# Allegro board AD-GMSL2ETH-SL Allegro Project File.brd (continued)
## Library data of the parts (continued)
R206 = RES: User Part Number: UPN; Tolerance: 5; alternate symbols: (R0402L); part number: RES_SM-510,E031796,1/10W,5,R0402; tolerance: 5
R221 R223 R225 = RES: User Part Number: UPN; Tolerance: 1; alternate symbols: (R0402); part number: RES_SM-100K,E003796,1/10W,1,R0402; tolerance: 1
R222 R224 = RES: User Part Number: UPN; Tolerance: 1; alternate symbols: (R0402); part number: RES_SM-15K,E007441,1/10W,1,R0402; tolerance: 1
R227 = RES: User Part Number: UPN; alternate symbols: (R0402L); part number: RES_SM-TBD0402,E004049,TBD0402,TBD0402,R0402
R229 = RES: User Part Number: UPN; Tolerance: 1; alternate symbols: (R0402L); part number: RES_SM-120K,E015615,1/10W,1,R0402; tolerance: 1
R238 = RES: User Part Number: UPN; Tolerance: 1; alternate symbols: (R0402L); part number: RES_SM-8.06K,E021385,1/10W,1,R0402; tolerance: 1
R242 = RES: User Part Number: UPN; Tolerance: 0.1; alternate symbols: (R0603); part number: RES_SM-82K,E040597,1/10W,0.1,R0603; tolerance: 0.1
R243 = RES: User Part Number: UPN; Tolerance: 1; alternate symbols: (R0603); part number: RES_SM-9.1K,E026628,1/10W,1,R0603; tolerance: 1
RT1-RT19 = RESTHERM: Tolerance: 20; User Part Number: UPN; alternate symbols: (R0603H35); part number: RESTHERM_SM-220,E023781,N/A,20,R0603H35; tolerance: 20
S1 S3 S6 = SWSPST4PIN_B: User Part Number: UPN; Tolerance: N/A; alternate symbols: (SWSMSQ236H169); part number: SWSPST4PIN_B_SM-PTS645SK43SMTR92LFS,E019205,SWSMSQ236H169; tolerance: N/A
S2 = SWITCH4: User Part Number: UPN; Tolerance: N/A; alternate symbols: (SWDIP8H335); part number: SWITCH4_TH-CTS206-4,E004560,SWDIP8H335; tolerance: N/A
S12 = SWSPDT: Tolerance: N/A; User Part Number: UPN; alternate symbols: (SWTHL500W260H511); part number: SWSPDT_TH-1101M2S3CQE2,E022397,SWTHL500W260H511; tolerance: N/A
TP1-TP3 TP5 = NCTESTPAD: Tolerance: N/A; User Part Number: UPN; alternate symbols: (TPSMC40); part number: NCTESTPAD_SM-TESTPAD,E019801,TPSMC40; tolerance: N/A
TP6 = CNTP1P: User Part Number: UPN; Tolerance: N/A; alternate symbols: (CNLOOPTP); part number: CNTP1P_TH-RED,E000947,CNLOOPTP; tolerance: N/A
U1 U2 = ADMAX96724: User Part Number: UPN; Tolerance: N/A; alternate symbols: (QFN56_8X8_PAD4_7X4_7H0_8); part number: ADMAX96724_SM-MAX96724GTN/VY+,E061473,QFN56_8X8_PAD4_7X4_7H0_8; tolerance: N/A
U3 = AD9545: User Part Number: UPN; Tolerance: N/A; alternate symbols: (QFN48_7X7_PAD5_6X5_6); part number: AD9545_SM-AD9545BCPZ,E022944,QFN48_7X7_PAD5_6X5_6; tolerance: N/A
U4-U6 U18 = ADLTC330X: User Part Number: UPN; Tolerance: N/A; alternate symbols: (QFN12_2X2_05-08-7072); part number: ADLTC330X_SM-LTC3303ARUCM#TRPBF,E059734,QFN12_2X2_05-08-7072; tolerance: N/A
U7 U8 = ADMAX3182X: Tolerance: N/A; User Part Number: UPN; alternate symbols: (WLCSP6H24); part number: ADMAX3182X_SM-MAX31827ANTABRPF+,E058070,WLCSP6H24; tolerance: N/A
U10 = ADMAX2520X: User Part Number: UPN; Tolerance: N/A; alternate symbols: (QFN20_4X4_PAD2_1X2_1); part number: ADMAX2520X_SM-MAX25206ATPA/VY+,E062128,QFN20_4X4_PAD2_1X2_1; tolerance: N/A
U12 U13 = ADMAX2008X: User Part Number: UPN; Tolerance: N/A; alternate symbols: (QFN20_4X4_PAD2_9X2_9); part number: ADMAX2008X_SM-MAX20087ATPA/VY+,E061551,QFN20_4X4_PAD2_9X2_9; tolerance: N/A
U14 = 741G126: User Part Number: UPN; Tolerance: N/A; alternate symbols: (SOT353); part number: 741G126_SM-74LVC1G126GW,E017822,SOT353; tolerance: N/A
U15 = IC24XX16: Tolerance: N/A; User Part Number: UPN; alternate symbols: (SO8); part number: IC24XX16_SM-24AA16-I/SN,E018010,SO8; tolerance: N/A
U17 = ADM7154: Tolerance: N/A; User Part Number: UPN; alternate symbols: (DFN8_3X3_PAD2_38X1_64); part number: ADM7154_SM-ADM7154ACPZ-3.3,E020267,DFN8_3X3_PAD2_38X1_64; tolerance: N/A
U19 = ICTCA9548A: Tolerance: N/A; User Part Number: UPN; alternate symbols: (QFN24_4X4_PAD2_1X2_1); part number: ICTCA9548A_SM-TCA9548ARGER,E022832,QFN24_4X4_PAD2_1X2_1; tolerance: N/A
U20 U25 = ICPCA9509: User Part Number: UPN; Tolerance: N/A; alternate symbols: (QFN8_1_6X1_6H20); part number: ICPCA9509_SM-PCA9509GM,125,E058249,QFN8_1_6X1_6H20; tolerance: N/A
U21 = ADMAX17573: User Part Number: UPN; Tolerance: N/A; alternate symbols: (QFN24_5X4_PAD3_65X2_65); part number: ADMAX17573_SM-MAX17573ATG+,E060644,QFN24_5X4_PAD3_65X2_65; tolerance: N/A
U22 = ICNVT4857: Tolerance: N/A; User Part Number: UPN; alternate symbols: (WLCSP20-2); part number: ICNVT4857_SM-NVT4857UKAZ,E046591,WLCSP20-2; tolerance: N/A
U23 = ICFT230XQ: Tolerance: N/A; User Part Number: UPN; alternate symbols: (QFN16_4X4_PAD2_1X2_1); part number: ICFT230XQ_SM-FT230XQ-R,E021729,QFN16_4X4_PAD2_1X2_1; tolerance: N/A
U24 = ICFXL2TD245: User Part Number: UPN; Tolerance: N/A; alternate symbols: (QFN10_2_1X1_6); part number: ICFXL2TD245_SM-FXL2TD245L10X,E017923,QFN10_2_1X1_6; tolerance: N/A
U26 = 7407_V4: User Part Number: UPN; Tolerance: N/A; alternate symbols: (SC70-6H43); part number: 7407_V4_SM-SN74LVC2G07DCKR,E055684,SC70-6H43; tolerance: N/A
U27 = ADLTC4355: User Part Number: UPN; Tolerance: N/A; alternate symbols: (DFN14_4X3_PAD3_3X1_7_05-08-1708); part number: ADLTC4355_SM-LTC4355IDE#PBF,E061026,DFN14_4X3_PAD3_3X1_7_05-08-1708; tolerance: N/A
Y1 Y2 = XTAL4PIN_V5: Tolerance: 30PPM; User Part Number: UPN; alternate symbols: (YSML126W98H31); part number: XTAL4PIN_V5_SM-25MEGHZ,E041019,YSML126W98H31; tolerance: 30PPM
Y3 = XTAL4PIN_V9: Tolerance: N/A; User Part Number: UPN; alternate symbols: (YSML79W63H20); part number: XTAL4PIN_V9_SM-52MEGHZ,E062914,YSML79W63H20; tolerance: N/A
Y4 = XTALOCXO4P: Tolerance: N/A; User Part Number: UPN; alternate symbols: (YSML382W295H169); part number: XTALOCXO4P_SM-50MEGHZ,E050311,YSML382W295H169; tolerance: N/A

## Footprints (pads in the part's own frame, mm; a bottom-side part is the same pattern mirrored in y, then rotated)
C0201
  rect 0.305x0.406 smd: 1(-0.318,0) 2(0.318,0)
C0402
  rect 0.483x0.559 smd: 1(-0.45,0) 2(0.45,0)
C0402#2
  rect 0.483x0.559 smd: 1(-0.438,0) 2(0.438,0)
C0402H22
  rect 0.559x0.508 smd: 1(-0.479,0) 2(0.479,0)
C0603
  rect 0.94x0.991 smd: 1(-0.8,0) 2(0.8,0)
C0603#2
  rect 0.762x0.889 smd: 1(-0.7,0) 2(0.7,0)
C0805
  rect 1.143x1.448 smd: 1(-0.9,0) 2(0.9,0)
C0805H53
  rect 1.295x1.6 smd: 1(-0.953,0) 2(0.953,0)
C0805H60
  rect 1.295x1.6 smd: 1(-0.953,0) 2(0.953,0)
C1206H71
  rect 1.6x2.007 smd: 1(-1.397,0) 2(1.397,0)
C1210H110
  rect 1.372x2.794 smd: 1(-1.431,0) 2(1.431,0)
C2220H98
  rect 1.549x5.41 smd: 1(-2.65,0) 2(2.65,0)
CNAMP1888-247
  round 2.794 hole 1.549 unplated: (-4.8,0) (4.8,0)
  rect 0.508x2.007 smd: 1(-3.4,-4.1) 2(-2.6,-4.1) 3(-1.8,-4.1) 4(-1,-4.1) 5(-0.2,-4.1) 6(0.6,-4.1) 7(1.4,-4.1) 8(2.2,-4.1) 9(3,-4.1) 10(3.8,-4.1) 11(3.4,4.1) 12(2.6,4.1) 13(1.8,4.1) 14(1,4.1) 15(0.2,4.1) 16(-0.6,4.1) 17(-1.4,4.1) 18(-2.2,4.1) 19(-3,4.1) 20(-3.8,4.1)
CNHDRRA2X3H451
  round 4.318 hole 2.997 unplated: (-0.013,7.29) (8.395,7.29)
  rect 2.286x2.286 hole 1.778: 1(0,0)
  round 2.286 hole 1.778: 2(4.191,0) 3(8.382,0) 4(0,-5.512) 5(4.191,-5.512) 6(8.382,-5.512)
CNHRSDM3BT-DSF-PEJS
  rect 0.711x1.397 smd: 1(-2.775,7.699) 2(-1.675,7.699) 3(-0.575,7.699) 4(0.525,7.699) 5(1.625,7.699) 6(2.725,7.699) 7(3.825,7.699) 8(4.925,7.699)
  rect 1.194x0.787 smd: A(6.725,-2.7)
  rect 0.711x1.194 smd: B(5.875,7.797)
  rect 0.991x1.397 smd: SH1(-4.675,7.699)
  rect 1.194x1.194 smd: SH2(6.725,3.5)
  rect 1.194x3.2 smd: SH3(6.725,-6.3)
  custom 0.476x0.476 smd: SH4(-6.325,-7.3)
CNJOHNSON142-0701-201
  round 2.032 hole 1.524: 1(0,0) 2(-2.54,2.54) 3(2.54,2.54) 4(2.54,-2.54) 5(-2.54,-2.54)
CNLOOPTP
  round 2.159 hole 1.6: 1(0,0)
CNMOLEX47590-0001
  oval 1.118x0.914 hole 0.864x0.66: (4.45,-2.225) (4.45,2.225)
  rect 1.346x0.406 smd: 1(4.123,-1.3) 2(4.123,-0.65) 3(4.123,0) 4(4.123,0.65) 5(4.123,1.3)
  oval 1.803x1.118 hole 1.295x0.61: SH1(1.45,4.175) SH3(1.45,-4.175)
  rect 1.905x2.896 smd: SH2(1.45,0)
CNMOLEX87832-1420
  round 1.27 hole 1.016 unplated: (-5,0) (5,0)
  rect 0.991x2.743 smd: 1(-6,-2.122) 2(-6,2.122) 3(-4,-2.122) 4(-4,2.122) 5(-2,-2.122) 6(-2,2.122) 7(0,-2.122) 8(0,2.122) 9(2,-2.122) 10(2,2.122) 11(4,-2.122) 12(4,2.122) 13(6,-2.122) 14(6,2.122)
CNPHOENIX1935161
  rect 1.905x1.905 hole 1.397: 1(0,0)
  round 1.905 hole 1.397: 2(5,0)
CNSAMTECTSW-108-08-G-D-ST
  rect 1.651x1.651 hole 1.143: 1(0,0)
  round 1.651 hole 1.143: 2(0,2.54) 3(2.54,0) 4(2.54,2.54) 5(5.08,0) 6(5.08,2.54) 7(7.62,0) 8(7.62,2.54) 9(10.16,0) 10(10.16,2.54) 11(12.7,0) 12(12.7,2.54) 13(15.24,0) 14(15.24,2.54) 15(17.78,0) 16(17.78,2.54)
CNSMMHDR4X60L1686W197H163
  round 1.27 hole 0.94 unplated: (-20.135,1.27) (20.135,0)
  round 0.356 smd: A1(18.73,1.75) A2(18.095,1.75) A3(17.46,1.75) A4(16.825,1.75) A5(16.19,1.75) A6(15.555,1.75) A7(14.92,1.75) A8(14.285,1.75) A9(13.65,1.75) A10(13.015,1.75) A11(12.38,1.75) A12(11.745,1.75) A13(11.11,1.75) A14(10.475,1.75) A15(9.84,1.75) A16(9.205,1.75) A17(8.57,1.75) A18(7.935,1.75) A19(7.3,1.75) A20(6.665,1.75) A21(6.03,1.75) A22(5.395,1.75) A23(4.76,1.75) A24(4.125,1.75) A25(3.49,1.75) A26(2.855,1.75) A27(2.22,1.75) A28(1.585,1.75) A29(0.95,1.75) A30(0.315,1.75) A31(-0.32,1.75) A32(-0.955,1.75) A33(-1.59,1.75) A34(-2.225,1.75) A35(-2.86,1.75) A36(-3.495,1.75) A37(-4.13,1.75) A38(-4.765,1.75) A39(-5.4,1.75) A40(-6.035,1.75) A41(-6.67,1.75) A42(-7.305,1.75) A43(-7.94,1.75) A44(-8.575,1.75) A45(-9.21,1.75) A46(-9.845,1.75) A47(-10.48,1.75) A48(-11.115,1.75) A49(-11.75,1.75) A50(-12.385,1.75) A51(-13.02,1.75) A52(-13.655,1.75) A53(-14.29,1.75) A54(-14.925,1.75) A55(-15.56,1.75) A56(-16.195,1.75) A57(-16.83,1.75) A58(-17.465,1.75) A59(-18.1,1.75) A60(-18.735,1.75) B1(18.73,0.79) B2(18.095,0.79) B3(17.46,0.79) B4(16.825,0.79) B5(16.19,0.79) B6(15.555,0.79) B7(14.92,0.79) B8(14.285,0.79) B9(13.65,0.79) B10(13.015,0.79) B11(12.38,0.79) B12(11.745,0.79) B13(11.11,0.79) B14(10.475,0.79) B15(9.84,0.79) B16(9.205,0.79) B17(8.57,0.79) B18(7.935,0.79) B19(7.3,0.79) B20(6.665,0.79) B21(6.03,0.79) B22(5.395,0.79) B23(4.76,0.79) B24(4.125,0.79) B25(3.49,0.79) B26(2.855,0.79) B27(2.22,0.79) B28(1.585,0.79) B29(0.95,0.79) B30(0.315,0.79) B31(-0.32,0.79) B32(-0.955,0.79) B33(-1.59,0.79) B34(-2.225,0.79) B35(-2.86,0.79) B36(-3.495,0.79) B37(-4.13,0.79) B38(-4.765,0.79) B39(-5.4,0.79) B40(-6.035,0.79) B41(-6.67,0.79) B42(-7.305,0.79) B43(-7.94,0.79) B44(-8.575,0.79) B45(-9.21,0.79) B46(-9.845,0.79) B47(-10.48,0.79) B48(-11.115,0.79) B49(-11.75,0.79) B50(-12.385,0.79) B51(-13.02,0.79) B52(-13.655,0.79) B53(-14.29,0.79) B54(-14.925,0.79) B55(-15.56,0.79) B56(-16.195,0.79) B57(-16.83,0.79) B58(-17.465,0.79) B59(-18.1,0.79) B60(-18.735,0.79) C1(18.73,-0.79) C2(18.095,-0.79) C3(17.46,-0.79) C4(16.825,-0.79) C5(16.19,-0.79) C6(15.555,-0.79) C7(14.92,-0.79) C8(14.285,-0.79) C9(13.65,-0.79) C10(13.015,-0.79) C11(12.38,-0.79) C12(11.745,-0.79) C13(11.11,-0.79) C14(10.475,-0.79) C15(9.84,-0.79) C16(9.205,-0.79) C17(8.57,-0.79) C18(7.935,-0.79) C19(7.3,-0.79) C20(6.665,-0.79) C21(6.03,-0.79) C22(5.395,-0.79) C23(4.76,-0.79) C24(4.125,-0.79) C25(3.49,-0.79) C26(2.855,-0.79) C27(2.22,-0.79) C28(1.585,-0.79) C29(0.95,-0.79) C30(0.315,-0.79) C31(-0.32,-0.79) C32(-0.955,-0.79) C33(-1.59,-0.79) C34(-2.225,-0.79) C35(-2.86,-0.79) C36(-3.495,-0.79) C37(-4.13,-0.79) C38(-4.765,-0.79) C39(-5.4,-0.79) C40(-6.035,-0.79) C41(-6.67,-0.79) C42(-7.305,-0.79) C43(-7.94,-0.79) C44(-8.575,-0.79) C45(-9.21,-0.79) C46(-9.845,-0.79) C47(-10.48,-0.79) C48(-11.115,-0.79) C49(-11.75,-0.79) C50(-12.385,-0.79) C51(-13.02,-0.79) C52(-13.655,-0.79) C53(-14.29,-0.79) C54(-14.925,-0.79) C55(-15.56,-0.79) C56(-16.195,-0.79) C57(-16.83,-0.79) C58(-17.465,-0.79) C59(-18.1,-0.79) C60(-18.735,-0.79) D1(18.73,-1.75) D2(18.095,-1.75) D3(17.46,-1.75) D4(16.825,-1.75) D5(16.19,-1.75) D6(15.555,-1.75) D7(14.92,-1.75) D8(14.285,-1.75) D9(13.65,-1.75) D10(13.015,-1.75) D11(12.38,-1.75) D12(11.745,-1.75) D13(11.11,-1.75) D14(10.475,-1.75) D15(9.84,-1.75) D16(9.205,-1.75) D17(8.57,-1.75) D18(7.935,-1.75) D19(7.3,-1.75) D20(6.665,-1.75) D21(6.03,-1.75) D22(5.395,-1.75) D23(4.76,-1.75) D24(4.125,-1.75) D25(3.49,-1.75) D26(2.855,-1.75) D27(2.22,-1.75) D28(1.585,-1.75) D29(0.95,-1.75) D30(0.315,-1.75) D31(-0.32,-1.75) D32(-0.955,-1.75) D33(-1.59,-1.75) D34(-2.225,-1.75) D35(-2.86,-1.75) D36(-3.495,-1.75) D37(-4.13,-1.75) D38(-4.765,-1.75) D39(-5.4,-1.75) D40(-6.035,-1.75) D41(-6.67,-1.75) D42(-7.305,-1.75) D43(-7.94,-1.75) D44(-8.575,-1.75) D45(-9.21,-1.75) D46(-9.845,-1.75) D47(-10.48,-1.75) D48(-11.115,-1.75) D49(-11.75,-1.75) D50(-12.385,-1.75) D51(-13.02,-1.75) D52(-13.655,-1.75) D53(-14.29,-1.75) D54(-14.925,-1.75) D55(-15.56,-1.75) D56(-16.195,-1.75) D57(-16.83,-1.75) D58(-17.465,-1.75) D59(-18.1,-1.75) D60(-18.735,-1.75)
CNTE2304168-X
  rect 1.168x1.168 hole 0.66: 1(0,0)
  round 1.168 hole 0.66: 2(0,-4) 3(4,-4) 4(4,0)
  round 2.032 hole 1.524: GND1(-2.35,-5.15) GND2(-2.35,1.25) GND3(6.35,-5.15) GND4(6.35,1.25)
  rect 0.991x3.302 smd: GND5(2,-4.501)
  rect 0.991x2.997 smd: GND6(2,0.249)
  rect 2.692x0.991 smd: GND7(-0.146,-2.05) GND8(4.146,-2.05)
  rect 1.041x3.607 smd: GND9(-2.641,-2.05) GND10(6.641,-2.05)
CNTHMHDR1X4L402W230H402
  round 1.778 hole 1.245 unplated: (5.08,2.16)
  rect 1.651x1.651 hole 1.143: 1(0,0)
  round 1.651 hole 1.143: 2(2.54,0) 3(5.08,0) 4(7.62,0)
CNTHMHDR2X4L400W200H330
  rect 1.651x1.651 hole 1.143: 1(0,0)
  round 1.651 hole 1.143: 2(0,2.54) 3(2.54,0) 4(2.54,2.54) 5(5.08,0) 6(5.08,2.54) 7(7.62,0) 8(7.62,2.54)
CPLSMSQ406H488
  rect 4.394x1.905 smd: N(4.347,0) P(-4.347,0)
D0201
  rect 0.229x0.381 smd: A(0.22,0) C(-0.22,0)
DFN8_3X3_PAD2_38X1_64
  oval 0.305x0.838 smd: 1(-0.75,-1.45) 2(-0.25,-1.45) 3(0.25,-1.45) 4(0.75,-1.45) 5(0.75,1.45) 6(0.25,1.45) 7(-0.25,1.45) 8(-0.75,1.45)
  rect 2.388x1.651 smd: PAD(0,0)
DFN14_4X3_PAD3_3X1_7_05-08-1708
  oval 0.254x0.914 smd: 1(-1.5,-1.557) 2(-1,-1.557) 3(-0.5,-1.557) 4(0,-1.557) 5(0.5,-1.557) 6(1,-1.557) 7(1.5,-1.557) 8(1.5,1.557) 9(1,1.557) 10(0.5,1.557) 11(0,1.557) 12(-0.5,1.557) 13(-1,1.557) 14(-1.5,1.557)
  rect 3.302x1.702 smd: 15(0,0)
DO214AB-4
  rect 2.388x3.277 smd: A(3.289,0) C(-3.289,0)
F1206H60
  rect 1.016x1.803 smd: 1(-1.41,0) 2(1.41,0)
FLSML476W358H146
  rect 3.81x2.489 smd: 1(-6.845,2.1) 2(6.845,2.1) 3(-6.845,-2.1) 4(6.845,-2.1)
  rect 7.899x2.311 smd: 5(1,-5.094)
  rect 3.404x2.311 smd: 6(3.25,5.094)
L0402
  rect 0.584x0.711 smd: 1(-0.475,0) 2(0.475,0)
L0806H39
  rect 0.787x1.6 smd: 1(-0.894,0) 2(0.894,0)
L1210H118
  rect 0.66x2.642 smd: 1(-1.27,0) 2(1.27,0)
L7144
  rect 0.635x1.016 smd: 1(-0.635,0) 2(0.635,0)
LED0603
  rect 0.965x0.762 smd: A(0.8,0) C(-0.8,0)
LSMSQ157H122
  rect 0.965x3.708 smd: 1(-1.181,0) 2(1.181,0)
LSMSQ236H98
  custom 0.575x0.575 smd: 1(-2.153,0) 2(2.153,0)
LSMSQ240H126
  custom 0.502x0.502 smd: 1(-2.756,0) 2(2.756,0)
MTE2007194-1
  round 1.524 hole 1.016: GND1(-4.795,6.2) GND2(0.005,6.2) GND3(4.805,6.2) GND5(7.125,1.6) GND6(7.125,-3.4) GND8(7.125,-8.1) GND15(-7.125,-8.1) GND16(-7.125,-3.4) GND18(-7.125,1.6)
  round 1.651 hole 1.143: GND4(7.125,4.1) GND7(7.125,-5.9) GND9(7.125,-15.9) GND10(7.125,-25.9) GND11(1.455,-30.9) GND12(-7.125,-30.9) GND13(-7.125,-20.9) GND14(-7.125,-10.9) GND19(-1.445,-10.9) GND20(3.955,-10.9)
  round 1.397 hole 0.889: GND17(-7.125,-0.9)
POWER33H31
  rect 0.432x0.711 smd: 1(-0.975,-1.404) 2(-0.325,-1.404) 3(0.325,-1.404) 4(0.975,-1.404)
  custom 0.54x0.54 smd: 5(0.97,1.531)
  round 0.127 smd: 6(0.325,1.535) 7(-0.325,1.535) 8(-0.975,1.535)
POWERPAKSO5
  rect 0.406x0.813 smd: 1(-1.905,-2.895) 2(-0.635,-2.895) 3(0.635,-2.895) 4(1.905,-2.895)
  custom 1.035x1.035 smd: 5(0,-0.18)
QFN8_1_6X1_6H20
  rect 0.305x0.406 smd: 1(-0.5,-0.6) 2(0,-0.6) 3(0.5,-0.6) 5(0.5,0.6) 6(0,0.6) 7(-0.5,0.6)
  rect 0.406x0.305 smd: 4(0.6,0) 8(-0.6,0)
QFN10_2_1X1_6
  rect 0.305x0.406 smd: 1(-0.75,-0.6) 2(-0.25,-0.6) 3(0.25,-0.6) 4(0.75,-0.6) 6(0.75,0.6) 7(0.25,0.6) 8(-0.25,0.6) 9(-0.75,0.6)
  rect 0.406x0.305 smd: 5(0.85,0) 10(-0.85,0)
QFN12_2X2_05-08-7072
  oval 0.711x0.254 smd: 1(-0.894,0.25)
  custom 0.165x0.165 smd: 2(-0.92,-0.25) 7(0.92,-0.25)
  round 0.127 smd: 3(-0.75,-0.906) 5(0.25,-0.906) 6(0.75,-0.906)
  custom 0.178x0.178 smd: 4(-0.229,-0.92)
  oval 0.66x0.254 smd: 8(0.92,0.25)
  oval 0.254x0.66 smd: 9(0.75,0.92) 10(0.25,0.92) 11(-0.25,0.92) 12(-0.75,0.92)
QFN16_4X4_PAD2_1X2_1
  oval 0.356x1.041 smd: 1(-0.975,-1.9) 2(-0.325,-1.9) 3(0.325,-1.9) 4(0.975,-1.9) 9(0.975,1.9) 10(0.325,1.9) 11(-0.325,1.9) 12(-0.975,1.9)
  oval 1.041x0.356 smd: 5(1.9,-0.975) 6(1.9,-0.325) 7(1.9,0.325) 8(1.9,0.975) 13(-1.9,0.975) 14(-1.9,0.325) 15(-1.9,-0.325) 16(-1.9,-0.975)
  rect 2.108x2.108 smd: PAD(0,0)
QFN20_4X4_PAD2_1X2_1
  oval 0.305x1.041 smd: 1(-1,-1.9) 2(-0.5,-1.9) 3(0,-1.9) 4(0.5,-1.9) 5(1,-1.9) 11(1,1.9) 12(0.5,1.9) 13(0,1.9) 14(-0.5,1.9) 15(-1,1.9)
  oval 1.041x0.305 smd: 6(1.9,-1) 7(1.9,-0.5) 8(1.9,0) 9(1.9,0.5) 10(1.9,1) 16(-1.9,1) 17(-1.9,0.5) 18(-1.9,0) 19(-1.9,-0.5) 20(-1.9,-1)
  rect 2.108x2.108 smd: PAD(0,0)
QFN20_4X4_PAD2_9X2_9
  oval 0.279x0.635 smd: 1(-1,-1.968) 2(-0.5,-1.968) 3(0,-1.968) 4(0.5,-1.968) 5(1,-1.968) 11(1,1.968) 12(0.5,1.968) 13(0,1.968) 14(-0.5,1.968) 15(-1,1.968)
  oval 0.635x0.279 smd: 6(1.968,-1) 7(1.968,-0.5) 8(1.968,0) 9(1.968,0.5) 10(1.968,1) 16(-1.968,1) 17(-1.968,0.5) 18(-1.968,0) 19(-1.968,-0.5) 20(-1.968,-1)
  rect 2.896x2.896 smd: PAD(0,0)
QFN24_4X4_PAD2_1X2_1
  oval 0.305x0.991 smd: 1(-1.25,-2) 2(-0.75,-2) 3(-0.25,-2) 4(0.25,-2) 5(0.75,-2) 6(1.25,-2) 13(1.25,2) 14(0.75,2) 15(0.25,2) 16(-0.25,2) 17(-0.75,2) 18(-1.25,2)
  oval 0.991x0.305 smd: 7(2,-1.25) 8(2,-0.75) 9(2,-0.25) 10(2,0.25) 11(2,0.75) 12(2,1.25) 19(-2,1.25) 20(-2,0.75) 21(-2,0.25) 22(-2,-0.25) 23(-2,-0.75) 24(-2,-1.25)
  rect 2.108x2.108 smd: PAD(0,0)
QFN24_5X4_PAD3_65X2_65
  oval 0.305x0.991 smd: 1(-1.5,-2.05) 2(-1,-2.05) 3(-0.5,-2.05) 4(0,-2.05) 5(0.5,-2.05) 6(1,-2.05) 7(1.5,-2.05) 13(1.5,2.05) 14(1,2.05) 15(0.5,2.05) 16(0,2.05) 17(-0.5,2.05) 18(-1,2.05) 19(-1.5,2.05)
  oval 0.991x0.305 smd: 8(2.55,-1) 9(2.55,-0.5) 10(2.55,0) 11(2.55,0.5) 12(2.55,1) 20(-2.55,1) 21(-2.55,0.5) 22(-2.55,0) 23(-2.55,-0.5) 24(-2.55,-1)
  rect 3.658x2.642 smd: PAD(0,0)
QFN48_7X7_PAD5_6X5_6
  oval 0.305x0.94 smd: 1(-2.75,-3.5) 2(-2.25,-3.5) 3(-1.75,-3.5) 4(-1.25,-3.5) 5(-0.75,-3.5) 6(-0.25,-3.5) 7(0.25,-3.5) 8(0.75,-3.5) 9(1.25,-3.5) 10(1.75,-3.5) 11(2.25,-3.5) 12(2.75,-3.5) 25(2.75,3.5) 26(2.25,3.5) 27(1.75,3.5) 28(1.25,3.5) 29(0.75,3.5) 30(0.25,3.5) 31(-0.25,3.5) 32(-0.75,3.5) 33(-1.25,3.5) 34(-1.75,3.5) 35(-2.25,3.5) 36(-2.75,3.5)
  oval 0.94x0.305 smd: 13(3.5,-2.75) 14(3.5,-2.25) 15(3.5,-1.75) 16(3.5,-1.25) 17(3.5,-0.75) 18(3.5,-0.25) 19(3.5,0.25) 20(3.5,0.75) 21(3.5,1.25) 22(3.5,1.75) 23(3.5,2.25) 24(3.5,2.75) 37(-3.5,2.75) 38(-3.5,2.25) 39(-3.5,1.75) 40(-3.5,1.25) 41(-3.5,0.75) 42(-3.5,0.25) 43(-3.5,-0.25) 44(-3.5,-0.75) 45(-3.5,-1.25) 46(-3.5,-1.75) 47(-3.5,-2.25) 48(-3.5,-2.75)
  rect 5.588x5.588 smd: PAD(0,0)
QFN56_8X8_PAD4_7X4_7H0_8
  oval 0.305x0.762 smd: 1(-3.25,-3.886) 2(-2.75,-3.886) 3(-2.25,-3.886) 4(-1.75,-3.886) 5(-1.25,-3.886) 6(-0.75,-3.886) 7(-0.25,-3.886) 8(0.25,-3.886) 9(0.75,-3.886) 10(1.25,-3.886) 11(1.75,-3.886) 12(2.25,-3.886) 13(2.75,-3.886) 14(3.25,-3.886) 29(3.25,3.886) 30(2.75,3.886) 31(2.25,3.886) 32(1.75,3.886) 33(1.25,3.886) 34(0.75,3.886) 35(0.25,3.886) 36(-0.25,3.886) 37(-0.75,3.886) 38(-1.25,3.886) 39(-1.75,3.886) 40(-2.25,3.886) 41(-2.75,3.886) 42(-3.25,3.886)
  oval 0.762x0.305 smd: 15(3.886,-3.25) 16(3.886,-2.75) 17(3.886,-2.25) 18(3.886,-1.75) 19(3.886,-1.25) 20(3.886,-0.75) 21(3.886,-0.25) 22(3.886,0.25) 23(3.886,0.75) 24(3.886,1.25) 25(3.886,1.75) 26(3.886,2.25) 27(3.886,2.75) 28(3.886,3.25) 43(-3.886,3.25) 44(-3.886,2.75) 45(-3.886,2.25) 46(-3.886,1.75) 47(-3.886,1.25) 48(-3.886,0.75) 49(-3.886,0.25) 50(-3.886,-0.25) 51(-3.886,-0.75) 52(-3.886,-1.25) 53(-3.886,-1.75) 54(-3.886,-2.25) 55(-3.886,-2.75) 56(-3.886,-3.25)
  rect 4.699x4.699 smd: PAD(0,0)
R0201
  rect 0.483x0.559 smd: 1(-0.45,0) 2(0.45,0)
R0402
  rect 0.483x0.559 smd: 1(-0.45,0) 2(0.45,0)
R0508
  rect 0.711x2.21 smd: 1(-0.656,0) 2(0.656,0)
R0603
  rect 0.787x0.991 smd: 1(-0.85,0) 2(0.85,0)
R0603#2
  rect 0.61x0.889 smd: 1(-0.75,0) 2(0.75,0)
R0603H35
  rect 0.813x0.813 smd: 1(-0.906,0) 2(0.906,0)
R0805
  rect 1.041x1.397 smd: 1(-0.95,0) 2(0.95,0)
R0805H20
  rect 0.94x1.448 smd: 1(-1,0) 2(1,0)
SC70-6H43
  rect 0.406x0.838 smd: 1(-0.65,-0.925) 2(0,-0.925) 3(0.65,-0.925) 4(0.65,0.925) 5(0,0.925) 6(-0.65,0.925)
SO8
  rect 0.61x2.184 smd: 1(-1.905,-2.54) 2(-0.635,-2.54) 3(0.635,-2.54) 4(1.905,-2.54) 5(1.905,2.54) 6(0.635,2.54) 7(-0.635,2.54) 8(-1.905,2.54)
SOD123-2
  rect 0.914x1.219 smd: A(1.638,0) C(-1.638,0)
SOD323-6
  rect 1.067x0.533 smd: A(1.073,0) C(-1.073,0)
SOT23
  rect 1.016x1.397 smd: 1(-0.94,-1.118) 2(0.94,-1.118) 3(0,1.118)
SOT223_A
  rect 0.889x1.803 smd: 1(-2.3,-3) 2(0,-3) 3(2.3,-3)
  rect 3.2x1.803 smd: 4(0,3)
SOT353
  rect 0.33x0.94 smd: 1(-0.65,-0.89) 2(0,-0.89) 3(0.65,-0.89) 4(0.65,0.89) 5(-0.65,0.89)
SOT416
  rect 0.61x0.686 smd: 1(-0.5,-0.533) 2(0.5,-0.533) 3(0,0.532)
SWDIP8H335
  rect 1.524x1.524 hole 1.016: 1A(0,0)
  round 1.524 hole 1.016: 1B(0,7.62) 2A(2.54,0) 2B(2.54,7.62) 3A(5.08,0) 3B(5.08,7.62) 4A(7.62,0) 4B(7.62,7.62)
SWSMSQ236H169
  rect 1.295x1.549 smd: 1(-2.25,-3.975) 2(-2.25,3.975) 3(2.25,-3.975) 4(2.25,3.975)
SWTHL500W260H511
  rect 2.286x2.286 hole 1.778: 1(0,0)
  round 2.286 hole 1.778: 2(4.699,0) 3(9.398,0)
TPSMC40
  round 1.016 smd: 1(0,0)
unnamed#2
  round 4.445 hole 3.175 unplated: (0,0)
WLCSP6H24
  round 0.292 smd: A1(-0.2,-0.4) A2(-0.2,0) A3(-0.2,0.4) B1(0.2,-0.4) B2(0.2,0) B3(0.2,0.4)
WLCSP20-2
  round 0.292 smd: A1(-0.8,-0.6) A2(-0.8,-0.2) A3(-0.8,0.2) A4(-0.8,0.6) B1(-0.4,-0.6) B2(-0.4,-0.2) B3(-0.4,0.2) B4(-0.4,0.6) C1(0,-0.6) C2(0,-0.2) C3(0,0.2) C4(0,0.6) D1(0.4,-0.6) D2(0.4,-0.2) D3(0.4,0.2) D4(0.4,0.6) E1(0.8,-0.6) E2(0.8,-0.2) E3(0.8,0.2) E4(0.8,0.6)
YSML79W63H20
  rect 0.94x0.838 smd: 1(-0.725,-0.575) 2(0.725,-0.575) 3(0.725,0.575) 4(-0.725,0.575)
YSML126W98H31
  rect 1.397x1.194 smd: 1(-1.1,-0.95) 2(1.1,-0.95) 3(1.1,0.95) 4(-1.1,0.95)
YSML382W295H169
  round 1.499 smd: 1(-3,-2) 2(3,-2) 3(3,2) 4(-3,2)

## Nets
1V2: C8.1 C11.1 C12.1 C13.1 C14.1 C70.1 C72.1 C73.1 C74.1 C75.1 C135.1 C138.1 C141.1 C163.1 C164.1 C165.1 L29.2(N2) P5.A44 P5.B42 P5.C44 P5.D42 R5.2(N2) R26.2(N2) R78.1 TP6.1(N1) U1.55 U1.56 U2.55 U2.56
1V8: C106.1 C110.1 C114.1 C123.1 C137.1 C140.1 C145.1 C235.1 C255.1 C263.1 D3.A(P) E1.2(N2) L28.2(N2) P3.D1 P3.D2 P5.B59 P5.B60 P5.D59 P5.D60 R1.1 R4.2(N2) R22.1 R25.2(N2) R36.1 R41.1 R70.1 R76.1 R113.1 R115.1 R117.1 R119.1 R120.1 R121.1 R129.1 R130.1 R131.1 R132.1 R134.1 R136.1 R137.1 R138.1 R142.1 R158.1 R166.1 R167.1 R168.1 R170.1 R172.1 R175.1 R177.1 R191.1 R218.1 R332.1 R333.1 U3.3 U19.21(VCC) U20.1 U22.A2 U24.10(VCCB) U25.1
3V3: C31.1 C32.1 C92.1 C93.1 C111.1 C115.1 C119.1 C124.1 C136.1 C139.1 C143.1 C144.1 C147.1 C156.1 C256.1 C257.1 D7.2 D8.2 D9.2 D10.2 D11.2 D12.2 D14.2 D15.2 D16.2 D17.2 D18.2 D19.2 D20.2 D21.2 D22.2 D23.2 D24.2 D25.2 DS6.A(P) DS8.A(P) DS9.A(P) DS10.A(P) L10.1 L11.1 L27.2(N2) P3.B13 P3.B14 P9.4 R38.1 R40.1 R42.1 R45.1 R48.1 R56.1 R59.1 R61.1 R69.1 R74.1 R80.1 R81.1 R82.1 R83.1 R124.1 R127.1 R133.1 R146.1 R147.1 R148.1 R150.1 R155.1 R179.1 R183.1 R184.1 R203.1 R248.1 U3.34 U7.A2(VDD) U8.A2(VDD) U12.11(VDD) U12.15 U13.11(VDD) U13.15 U15.8 U20.8(VCCB) U22.A3(VSD) U25.8(VCCB)
3V3_FT232R: C258.1 C261.1 C262.1 U23.1(VCCIO) U23.8 U24.1 U24.4
3V3_SFP_RX: C2.1 C254.1 L10.2(N2) P4.15
3V3_SFP_TX: C1.1 C3.1 L11.2(N2) P4.16
3V8: C146.1 C226.1 C274.1 C275.1 L32.2(N2) R229.1 U17.7 U17.8
5V: C129.1 C130.1 C131.1 C132.1 C133.1 C134.1 C159.1 C160.1 C161.1 C162.1 C231.1 C232.1 C250.1 C271.1 C273.1 D1.C D6.2 DS11.A(P) P3.A59 P3.A60 P3.B60 P3.C59 P3.C60 P3.D60 P6.2 R29.1 R71.1 R72.1 R73.1 R100.1 R101.1 R109.2(N2) R111.1 R112.1 R220.1 R228.1 U4.2 U4.3(VIN_2) U5.2 U5.3(VIN_2) U6.2 U6.3(VIN_2) U18.2 U18.3(VIN_2) U26.5(VCC)
5V_BIAS: C228.1 R93.1 R96.1 R110.2(N2) U10.13
5V_SYNCOUT: R240.2(N2) U10.2(SYNCOUT)
9V_FB: R242.2(N2) R243.1 U21.18
GND: C1.2(N2) C2.2(N2) C3.2(N2) C4.2(N2) C5.2(N2) C6.2(N2) C7.2(N2) C8.2(N2) C9.2(N2) C10.2(N2) C11.2(N2) C12.2(N2) C13.2(N2) C14.2(N2) C15.2(N2) C16.2(N2) C17.2(N2) C18.2(N2) C19.2(N2) C20.2(N2) C21.2(N2) C22.2(N2) C23.2(N2) C24.2(N2) C25.2(N2) C26.2(N2) C27.2(N2) C28.2(N2) C29.2(N2) C30.2(N2) C31.2(N2) C32.2(N2) C33.2(N2) C34.2(N2) C35.2(N2) C36.2(N2) C37.2(N2) C38.2(N2) C39.2(N2) C40.2(N2) C49.2(N2) C50.2(N2) C51.2(N2) C52.2(N2) C53.2(N2) C54.2(N2) C55.2(N2) C56.2(N2) C65.2(N2) C66.2(N2) C67.2(N2) C68.2(N2) C69.2(N2) C70.2(N2) C71.2(N2) C72.2(N2) C73.2(N2) C74.2(N2) C75.2(N2) C76.2(N2) C77.2(N2) C78.2(N2) C79.2(N2) C80.2(N2) C81.2(N2) C82.2(N2) C83.2(N2) C84.2(N2) C85.2(N2) C86.2(N2) C87.2(N2) C88.2(N2) C89.2(N2) C90.2(N2) C91.2(N2) C92.2(N2) C93.2(N2) C94.2(N2) C95.2(N2) C96.2(N2) C97.2(N2) C98.2(N2) C99.2(N2) C101.2(N2) C102.2(N2) C103.2(N2) C104.2(N2) C105.2(N2) C106.2(N2) C107.2(N2) C108.1 C109.2(N2) C110.2(N2) C111.2(N2) C112.2(N2) C114.2(N2) C115.2(N2) C116.2(N2) C117.2(N2) C118.2(N2) C119.2(N2) C120.1 C122.1 C123.2(N2) C124.2(N2) C129.2(N2) C130.2(N2) C131.2(N2) C132.2(N2) C133.2(N2) C134.2(N2) C136.2(N2) C137.2(N2) C138.2(N2) C139.2(N2) C140.2(N2) C141.2(N2) C143.2(N2) C144.2(N2) C148.1 C151.1 C152.2(N2) C153.2(N2) C154.2(N2) C155.2(N2) C156.2(N2) C157.2(N2) C158.2(N2) C159.2(N2) C160.2(N2) C161.2(N2) C162.2(N2) C163.2(N2) C164.2(N2) C165.2(N2) C222.N(N2) C223.2(N2) C224.2(N2) C225.2(N2) C226.2(N2) C227.2(N2) C228.2(N2) C231.2(N2) C232.2(N2) C233.2(N2) C234.2(N2) C235.2(N2) C245.2(N2) C246.2(N2) C248.2(N2) C249.2(N2) C250.2(N2) C251.2(N2) C252.2(N2) C253.2(N2) C254.2(N2) C255.2(N2) C256.2(N2) C257.2(N2) C258.2(N2) C259.2(N2) C260.2(N2) C261.2(N2) C262.2(N2) C263.2(N2) C267.1 C268.1 C271.2(N2) C272.2(N2) C273.2(N2) C274.2(N2) C275.2(N2) D2.A(P) D4.A(P) D5.A(P) D6.1 D7.1 D8.1 D9.1 D10.1 D11.1 D12.1 D13.A(P) D14.1 D15.1 D16.1 D17.1 D18.1 D19.1 D20.1 D21.1 D22.1 D23.1 D24.1 D25.1 FL1.4 FL1.5 FL1.6 J1.2 J1.3 J1.4 J1.5(SH4) J2.2 J2.3 J2.4 J2.5(SH4) J3.2 J3.3 J3.4 J3.5(SH4) J4.2 J4.3 J4.4 J4.5(SH4) M4.GND1 M4.GND2 M4.GND3 M4.GND4 M4.GND5 M4.GND6 M4.GND7 M4.GND8 M4.GND9(CGND9) M4.GND10 M4.GND11 M4.GND12 M4.GND13 M4.GND14 M4.GND15 M4.GND16 M4.GND17 M4.GND18 M4.GND19 M4.GND20 P1.GND1 P1.GND2 P1.GND3 P1.GND4 P1.GND5(N9) P1.GND6 P1.GND7 P1.GND8 P1.GND9 P1.GND10 P2.GND1 P2.GND2 P2.GND3 P2.GND4 P2.GND5(N9) P2.GND6 P2.GND7 P2.GND8 P2.GND9 P2.GND10 P3.A2 P3.A5 P3.A8 P3.A11 P3.A14 P3.A18 P3.A21 P3.A26 P3.A33 P3.A37 P3.A41 P3.A45 P3.A46 P3.A49 P3.A50 P3.A53 P3.A54 P3.A57 P3.A58 P3.B3 P3.B6 P3.B9 P3.B12 P3.B15 P3.B19 P3.B23 P3.B27 P3.B31 P3.B35 P3.B39 P3.B43 P3.B47 P3.B48 P3.B51 P3.B52 P3.B55 P3.B56 P3.B59 P3.C1 P3.C2 P3.C5 P3.C8 P3.C11 P3.C14 P3.C17 P3.C21 P3.C25 P3.C29 P3.C33 P3.C37 P3.C41 P3.C46 P3.C49 P3.C50 P3.C53 P3.C54 P3.C57 P3.C58 P3.D3 P3.D6 P3.D9(N9) P3.D12 P3.D15 P3.D19 P3.D23 P3.D27 P3.D31 P3.D35 P3.D39 P3.D43 P3.D47 P3.D48 P3.D51 P3.D52 P3.D55 P3.D56 P3.D59 P4.1 P4.10 P4.11 P4.14 P4.17 P4.20 P5.A1 P5.A2 P5.A5 P5.A6 P5.A9 P5.A10 P5.A13 P5.A16 P5.A19 P5.A22 P5.A25 P5.A28 P5.A31 P5.A34 P5.A37 P5.A40 P5.A43 P5.A45 P5.A49 P5.A53 P5.A57 P5.B3 P5.B4 P5.B7 P5.B8 P5.B11 P5.B14 P5.B17 P5.B20 P5.B23 P5.B26 P5.B29 P5.B32 P5.B35 P5.B38 P5.B41 P5.B43 P5.B47 P5.B51 P5.B55 P5.C1 P5.C2 P5.C5 P5.C6 P5.C9 P5.C10 P5.C13 P5.C16 P5.C19 P5.C22 P5.C25 P5.C28 P5.C31 P5.C34 P5.C37 P5.C40 P5.C43 P5.C45 P5.C49 P5.C53 P5.C57 P5.D3 P5.D4 P5.D7 P5.D8 P5.D11 P5.D14 P5.D17 P5.D20 P5.D23 P5.D26 P5.D29 P5.D32 P5.D35 P5.D38 P5.D41 P5.D43 P5.D47 P5.D51 P5.D55 P6.1 P7.1 P7.3 P7.5 P7.7 P7.9(N9) P7.11 P7.13 P8.1 P9.6 P9.B P9.SH1 P9.SH2 P9.SH3 P9.SH4 P10.5 P13.1 P13.2 P13.4 P13.6 P13.8(N8) Q1.3(S) Q2.2(S) Q3.2(S) Q5.1 Q5.2 Q5.3(S3) Q6.2(S) Q12.2(S) Q13.2(S) R2.1 R6.2(N2) R7.2(N2) R12.2(N2) R13.2(N2) R14.2(N2) R15.2(N2) R20.2(N2) R21.2(N2) R23.1 R30.2(N2) R39.2(N2) R43.1 R49.2(N2) R50.2(N2) R51.2(N2) R60.2(N2) R62.2(N2) R63.2(N2) R64.2(N2) R65.2(N2) R66.2(N2) R67.2(N2) R68.2(N2) R75.2(N2) R77.2(N2) R79.2(N2) R84.2(N2) R85.2(N2) R94.2(N2) R95.2(N2) R97.2(N2) R99.2(N2) R104.2(N2) R114.2(N2) R116.2(N2) R118.2(N2) R149.2(N2) R152.2(N2) R157.2(N2) R165.2(N2) R169.2(N2) R171.2(N2) R176.2(N2) R178.2(N2) R180.2(N2) R182.2(N2) R190.2(N2) R199.2(N2) R201.2(N2) R204.2(N2) R206.2(N2) R219.2(N2) R222.2(N2) R224.2(N2) R225.2(N2) R227.2(N2) R230.2(N2) R237.2(N2) R238.2(N2) R241.2(N2) R243.2(N2) R247.2(N2) R251.2(N2) S12.3(NO) U1.PAD U2.PAD U3.PAD U4.6 U4.7 U4.8 U4.11 U5.6 U5.7 U5.8 U5.11 U6.6 U6.7 U6.8 U6.11 U7.A3 U8.A3 U10.7 U10.12 U10.14 U10.PAD U12.1 U12.5 U12.9 U12.12 U12.16 U12.PAD U13.1 U13.5 U13.9 U13.12 U13.16 U13.PAD U14.3 U15.4 U17.4 U17.PAD U18.6 U18.7 U18.8 U18.11 U19.9 U19.PAD U20.4 U21.2 U21.3 U21.11 U21.20 U21.21 U21.PAD U22.C2 U22.C3 U23.3 U23.13 U23.PAD U24.5 U24.6 U24.7 U25.4 U26.2 U27.7 U27.10 U27.11 U27.12 U27.13 U27.15 Y1.2 Y1.4 Y2.2 Y2.4 Y3.2 Y3.4 Y4.2
VBUS_USB_DEBUG: C259.1 C260.1 D2.C P10.1 R181.1 U23.10
VCC_IN: C222.P C223.1 C224.1 C245.1 C246.1 Q4.5 Q4.6 Q4.7 Q4.8 Q7.5 Q8.5 Q8.6 Q8.7 Q8.8 R211.1 TP5.1(N1) U10.19 U21.5 U21.6 U21.7 U21.9 U27.3
VCC_IN_1: D13.C F1.2(N2) Q4.1 Q4.2 Q4.3(S3) R223.1 U27.1
VCCOEN_PL_M2C: P3.A20 R51.1 U26.3
VCCOEN_PS_M2C: P3.A19 R50.1 U26.1
VDD_ANALOG: C94.1 C95.1 C97.1 C98.1 C99.1 C101.1 C102.1 C103.1 C104.1 C105.1 C157.1 C158.1 E1.1 R55.2(N2) R57.2(N2) R88.2(N2) R89.2(N2) R139.2(N2) U3.6 U3.9 U3.10 U3.13 U3.19 U3.20 U3.24 U3.27 U3.28 U3.31 U3.40 U3.41 U3.45 U14.1 U14.5
VDDOCXO_3V3: C112.1 C117.1 E2.2(N2) Y4.4(VCC)
1PPS_IN: D6.3(N3) R185.1 RT19.1
A_CAPVDD: C7.1 C9.1 C15.1 C16.1 U1.8 U1.20
A_CFG0: R145.1 U1.4
A_CKAN/CKDN/A3A/D1A: P5.D16 U1.40
A_CKAP/CKDP/A2C/D0C: P5.D15 U1.39
A_CKBN/CKEN/B1A/E1A: P5.B13 U1.46
A_CKBP/CKEP/B0C/E0C: P5.B12 U1.45
A_DA0N/DC0N/A0B/C0B: P5.D13 U1.32
A_DA0P/DC0P/A0A/C0A: P5.D12 U1.31
A_DA1N/DC1N/A1C/C1C: P5.C18 U1.36
A_DA1P/DC1P/A1B/C1B: P5.C17 U1.35
A_DA2N/DD0N/A2B/D0B: P5.B25 U1.38
A_DA2P/DD0P/A2A/D0A: P5.B24 U1.37
A_DA3N/DD1N/A3C/D1C: P5.D22 U1.42
A_DA3P/DD1P/A3B/D1B: P5.D21 U1.41
A_DB0N/DE0N/B0B/E0B: P5.B22 U1.44
A_DB0P/DE0P/B0A/E0A: P5.B21 U1.43
A_DB1N/DE1N/B1C/E1C: P5.A18 U1.48
A_DB1P/DE1P/B1B/E1B: P5.A17 U1.47
A_DB2N/DF0N/B2B/F0B: P5.C21 U1.50
A_DB2P/DF0P/B2A/F0A: P5.C20 U1.49
A_DB3N/DF1N/B3C/F1C: P5.C15 U1.54
A_DB3P/DF1P/B3B/F1B: P5.C14 U1.53
A_GMSL-PWDNB: P5.B44 R154.1 U1.11
A_MFP0/LMN0/FSYNC: P5.A46 U1.1
A_MFP1/LMN1/VS0/DE0/HS0: P5.A47 U1.2
A_MFP2/LMN2: P5.A48 U1.3
A_MFP3/LMN3/VS1/DE1/HS1: P5.B45 U1.12
A_MFP4/LOCK: P5.B46 U1.13
A_MFP5/ERRB: P5.C46 U1.14
A_MFP6/CFG1: P5.C47 R151.1 U1.25
A_MFP7: P5.D45 R125.2(N2)
A_MFP7/SDA1_RX1: R125.1 R167.2(N2) U1.26 U20.2
A_MFP8: P5.D44 R126.2(N2)
A_MFP8/SCL1_TX1: R126.1 R166.2(N2) U1.27 U20.3
A_SCL: R129.2(N2) U1.29 U19.8
A_SDA: R134.2(N2) U1.28 U19.7
A_SIOAN: C41.1 U1.22
A_SIOAP: C45.2(N2) U1.23
A_SIOBN: C42.1 U1.19
A_SIOBP: C46.2(N2) U1.18
A_SIOCN: C43.1 U1.9
A_SIOCP: C47.2(N2) U1.10
A_SIODN: C44.1 U1.6
A_SIODP: C48.2(N2) U1.5
A_VDD18: C4.1 C5.1 C6.1 C18.1 C19.1 C152.1 R1.2(N2) U1.7 U1.21
A_VPOC_1: C28.1 R189.1 U12.6
A_VPOC_2: C27.1 R192.1 U12.20
A_VPOC_3: C29.1 R193.1 U12.7
A_VPOC_4: C30.1 R194.1 U12.19
A_VTERM: C23.1 C24.1 C25.1 R5.1 U1.30
AD9545_OUT0B_N: P3.C13 R91.2(N2)
AD9545_OUT0B_P: P3.C12 R90.2(N2)
AD9545_OUT1A_N: P3.A7 R140.2(N2)
AD9545_OUT1A_P: P3.A6 R217.2(N2)
AD9545_OUT1B_N: P3.B11 R144.2(N2)
AD9545_OUT1B_P: P3.B10 R143.2(N2)
B_CAPVDD: C68.1 C69.1 C76.1 C77.1 U2.8 U2.20
B_CFG0: R156.1 U2.4
B_CKAN/CKDN/A3A/D1A: P5.B19 U2.40
B_CKAP/CKDP/A2C/D0C: P5.B18 U2.39
B_CKBN/CKEN/B1A/E1A: P5.A12 U2.46
B_CKBP/CKEP/B0C/E0C: P5.A11 U2.45
B_DA0N/DC0N/A0B/C0B: P5.A21 U2.32
B_DA0P/DC0P/A0A/C0A: P5.A20 U2.31
B_DA1N/DC1N/A1C/C1C: P5.B16 U2.36
B_DA1P/DC1P/A1B/C1B: P5.B15 U2.35
B_DA2N/DD0N/A2B/D0B: P5.A15 U2.38
B_DA2P/DD0P/A2A/D0A: P5.A14 U2.37
B_DA3N/DD1N/A3C/D1C: P5.C12 U2.42
B_DA3P/DD1P/A3B/D1B: P5.C11 U2.41
B_DB0N/DE0N/B0B/E0B: P5.A24 U2.44
B_DB0P/DE0P/B0A/E0A: P5.A23 U2.43
B_DB1N/DE1N/B1C/E1C: P5.D25 U2.48
B_DB1P/DE1P/B1B/E1B: P5.D24 U2.47
B_DB2N/DF0N/B2B/F0B: P5.C24 U2.50
B_DB2P/DF0P/B2A/F0A: P5.C23 U2.49
B_DB3N/DF1N/B3C/F1C: P5.A27 U2.54
B_DB3P/DF1P/B3B/F1B: P5.A26 U2.53
B_GMSL-PWDNB: P5.B48 R187.1 U2.11
B_MFP0/LMN0/FSYNC: P5.A50 U2.1
B_MFP1/LMN1/VS0/DE0/HS0: P5.A51 U2.2
B_MFP2/LMN2: P5.A52 U2.3
B_MFP3/LMN3/VS1/DE1/HS1: P5.B49 U2.12
B_MFP4/LOCK: P5.B50 U2.13
B_MFP5/ERRB: P5.C48 U2.14
B_MFP6/CFG1: P5.C50 R186.1 U2.25
B_MFP7: P5.D48 R173.2(N2)
B_MFP7/SDA1_RX1: R173.1 R175.2(N2) U2.26 U25.2
B_MFP8: P5.D46 R174.2(N2)
B_MFP8/SCL1_TX1: R158.2(N2) R174.1 U2.27 U25.3
B_SCL: R137.2(N2) U2.29 U19.11
B_SDA: R138.2(N2) U2.28 U19.10
B_SIOAN: C57.1 U2.22
B_SIOAP: C63.2(N2) U2.23
B_SIOBN: C58.1 U2.19
B_SIOBP: C64.2(N2) U2.18
B_SIOCN: C59.1 U2.9
B_SIOCP: C61.2(N2) U2.10
B_SIODN: C60.1 U2.6
B_SIODP: C62.2(N2) U2.5
B_VDD18: C65.1 C66.1 C67.1 C79.1 C80.1 C154.1 R22.2(N2) U2.7 U2.21
B_VPOC_1: C89.1 R216.1 U13.6
B_VPOC_2: C88.1 R231.1 U13.20
B_VPOC_3: C90.1 R214.1 U13.7
B_VPOC_4: C91.1 R215.1 U13.19
B_VTERM: C84.1 C85.1 C86.1 R26.1 U2.30
BTN0_USER: P5.C52 R218.2(N2) S3.1 S3.2
EN_5V0: C272.1 R141.1 R211.2(N2) R226.2(N2) U10.20 U21.10
EN_I2C_ALT: P5.A54 R41.2(N2) U20.5 U25.5
EN_VIO: R220.2(N2) U4.1 U5.1 U6.1 U18.1 U26.4 U26.6
FAN_PWM: P3.C23 R98.1
FAN_TACH: P3.C22 R103.2(N2) R104.1
GPIO_0: D7.3(N3) P3.A15 RT3.2(N2)
GPIO_1: D8.3(N3) P3.A16 RT4.2(N2)
GPIO_2: D9.3(N3) P3.A17 RT5.2(N2)
GPIO_3: D10.3(N3) P3.B16 RT6.2(N2)
GPIO_4: D11.3(N3) P3.B17 RT7.2(N2)
GPIO_5: D12.3(N3) P3.B18 RT8.2(N2)
GPIO_6: D14.3(N3) P3.C18 RT11.2(N2)
GPIO_7: D15.3(N3) P3.C19 RT12.2(N2)
GPIO_8: D16.3(N3) P3.C20 RT13.2(N2)
GPIO_9: D17.3(N3) P3.D16 RT14.2(N2)
GPIO_10: D18.3(N3) P3.D17 RT15.2(N2)
GPIO_11: D19.3(N3) P3.D18 RT16.2(N2)
GTH_REFLCK_N: C128.2(N2) P5.C4
GTH_REFLCK_P: C127.2(N2) P5.C3
I2C_EXP_RSTB: P5.C51 R121.2(N2) U19.24
I2C_MASTER_SCL: R45.2(N2) R54.2(N2) U3.33
I2C_MASTER_SDA: R42.2(N2) R58.2(N2) U3.35
I2C_SCK: P5.D49 R119.2(N2) R122.1
I2C_SDA: P5.D50 R120.2(N2) R123.1
JTAG_TCK: P3.A25 P7.6
JTAG_TDI: P3.A24 P7.10
JTAG_TDO: P3.A23 P7.8
JTAG_TMS: P3.A22 P7.4
LDO_OUT: C249.1 R239.2(N2) U21.12(VCC)
LED0_USER: P5.B53 Q3.1 R152.1
LX1: C247.1 L33.1 U21.1 U21.23 U21.24
MIO36_TXD: P3.B29 U24.8
MIO37_RXD: P3.B30 U24.9
OUT0_A_N: C128.1 R53.2(N2) U3.12
OUT0_A_P: C127.1 R52.1 U3.11
OUT0_B_N: R87.2(N2) R91.1 U3.15
OUT0_B_P: R86.1 R90.1 U3.14
OUT0_C_N: C150.1 R208.2(N2) U3.18
OUT0_C_P: C149.1 R207.2(N2) U3.17
OUT1_A_N: R47.2(N2) R140.1 U3.26
OUT1_A_P: R46.1 R217.1 U3.25
OUT1_B_N: R128.2(N2) R144.1 U3.23
OUT1_B_P: R92.1 R143.1 U3.22
PGOOD_VIO: Q13.1 R248.2(N2) U4.9 U5.9 U6.9 U18.9
PS_ERROR_OUT: P3.B24 Q6.1 R199.1
PS_ERROR_STATUS: P3.B25 Q12.1 R201.1
PS_MIO39_501_SDIO_SEL: P3.B33 U22.E3
PS_MIO45_501_SDIO_DETECT: P3.D33 P9.A R136.2(N2) U22.B2
PS_MIO46_501_SDIO_DAT0: R164.1 R332.2(N2) U22.D1
PS_MIO47_501_SDIO_DAT1: R132.2(N2) R162.1 U22.E1
PS_MIO48_501_SDIO_DAT2: R131.2(N2) R161.1 U22.A1
PS_MIO49_501_SDIO_DAT3: R130.2(N2) R163.1 U22.B1
PS_MIO50_501_SDIO_CMD: R160.1 R333.2(N2) U22.C1
PS_MIO51_501_SDIO_CLK: R159.1 U22.D2
PS_MODE0: P3.A27 S2.1A
PS_MODE1: P3.A28 S2.2A
PS_MODE2: P3.A29 S2.3A
PS_MODE3: P3.A30 S2.4A(N4)
PS_POR_L: P3.C15 S6.1 S6.2
PS_SRST_B: P3.C16 S1.1 S1.2
PWROFF_C2M_L: P3.B26 R100.2(N2) R249.1 R250.1
REF_AD9545_EXT: R31.2(N2) U3.38
REF_AD9545_PL: P3.B1 R188.1
REF_PPS_IN: R37.2(N2) U3.39
RESETB_AD9545: P3.B7 R191.2(N2) U3.48
RXD_FT232: U23.2 U24.3
SCL_A_ALT: D21.3(N3) R124.2(N2) RT9.2(N2) U20.6
SCL_A_VCAM: R179.2(N2) U12.14 U19.2
SCL_B_ALT: D24.3(N3) R155.2(N2) RT10.2(N2) U25.6
SCL_B_VCAM: R184.2(N2) U13.14 U19.4
SCL_TEMP1: R80.2(N2) U7.B2 U19.13
SCL_TEMP2: R81.2(N2) U8.B2 U19.15
SDA_A_ALT: D20.3(N3) R56.2(N2) RT1.2(N2) U20.7
SDA_A_VCAM: R183.2(N2) U12.13 U19.1
SDA_B_ALT: D22.3(N3) R69.2(N2) RT2.2(N2) U25.7
SDA_B_VCAM: R203.2(N2) U13.13 U19.3
SDA_TEMP1: R82.2(N2) U7.B1 U19.12
SDA_TEMP2: R83.2(N2) U8.B1 U19.14
SDIO_CLK: P9.5 U22.D3
SDIO_CMD: P9.3 U22.C4
SDIO_DAT0: P9.7 U22.D4
SDIO_DAT1: P9.8 U22.E4
SDIO_DAT2: P9.1 U22.A4
SDIO_DAT3: P9.2 R135.2(N2) U22.B4
SFP+_I2C_SCL_3V3: P4.5 R127.2(N2) U19.6
SFP+_I2C_SDA_3V3: P4.4 R133.2(N2) U19.5
SFP+_LOS_3V3: P4.8 R148.2(N2) TP2.1(N1)
SFP+_MOD_DETECT_3V3: P4.6 R150.2(N2) TP3.1(N1)
SFP+_RS0_3V3: P4.7 R59.2(N2) R60.1
SFP+_RS1_3V3: P4.9(N9) R61.2(N2) R62.1
SFP+_RX_N: C126.1 P5.B2
SFP+_RX_P: C121.1 P5.B1
SFP+_TX_DISABLE: P5.B52 Q2.1 R149.1
SFP+_TX_DISABLE_3V3: P4.3 Q2.3 R146.2(N2) R251.1
SFP+_TX_FAULT_3V3: P4.2 R147.2(N2) TP1.1(N1)
SFP+_TX_N: C125.1 P5.B6
SFP+_TX_P: C142.1 P5.B5
SPI_CS_AD9545: P3.B5 R35.1
SPI_MISO: P3.A3 R32.1
SPI_MOSI: P3.B4 R34.1
SPI_SCL: P3.A4 R33.1
TXD_FT232: U23.15 U24.2
UART_RXD: D23.3(N3) P3.D20 RT17.1
UART_TXD: D25.3(N3) P3.D21 RT18.1
UNNAMED_2_ADMAX2008X_I77_ISET: R157.1 U12.10
UNNAMED_2_ADMAX96724_I1_VDDIO: C20.1 C21.1 C22.1 R4.1 U1.24
UNNAMED_2_ADMAX96724_I1_X1: C10.1 U1.15 Y1.1
UNNAMED_2_ADMAX96724_I1_X2: R3.2(N2) U1.16
UNNAMED_2_ADMAX96724_I1_XRES: R2.2(N2) U1.17(XRES)
UNNAMED_2_CAP_I50_N1: C17.1 R3.1 Y1.3(IN/OUT2)
UNNAMED_2_CAP_I106_N1: C153.1 R154.2(N2) R172.2(N2)
UNNAMED_2_RES_I103_N2: R145.2(N2) R168.2(N2) R169.1
UNNAMED_2_RES_I104_N2: R151.2(N2) R170.2(N2) R171.1
UNNAMED_3_ADMAX2008X_I69_ISET: R165.1 U13.10
UNNAMED_3_ADMAX96724_I1_VDDIO: C81.1 C82.1 C83.1 R25.1 U2.24
UNNAMED_3_ADMAX96724_I1_X1: C71.1 U2.15 Y2.1
UNNAMED_3_ADMAX96724_I1_X2: R24.2(N2) U2.16
UNNAMED_3_ADMAX96724_I1_XRES: R23.2(N2) U2.17(XRES)
UNNAMED_3_CAP_I74_N1: C78.1 R24.1 Y2.3(IN/OUT2)
UNNAMED_3_CAP_I103_N1: C155.1 R115.2(N2) R187.2(N2)
UNNAMED_3_RES_I100_N2: R70.2(N2) R156.2(N2) R176.1
UNNAMED_3_RES_I101_N2: R177.2(N2) R178.1 R186.2(N2)
UNNAMED_4_ICTCA9548A_I28_A0: R117.2(N2) R118.1 U19.22
UNNAMED_4_ICTCA9548A_I28_A1: R116.1 R142.2(N2) U19.23
UNNAMED_4_ICTCA9548A_I28_A2: R113.2(N2) R114.1 U19.18
UNNAMED_4_ICTCA9548A_I28_SCL: R122.2(N2) U19.19
UNNAMED_4_ICTCA9548A_I28_SDA: R123.2(N2) U19.20
UNNAMED_5_CAP_I2_N1: C36.1 C40.1 L4.1 R194.2(N2) R198.2(N2) R213.1
UNNAMED_5_CAP_I7_N1: C35.1 C39.1 L3.1 R193.2(N2) R197.2(N2) R212.1
UNNAMED_5_CAP_I12_N1: C34.1 C38.1 L2.1 R192.2(N2) R196.2(N2) R210.1
UNNAMED_5_CAP_I31_N1: C33.1 C37.1 L1.1 R189.2(N2) R195.2(N2) R209.1
UNNAMED_5_CAP_I42_N1: C50.1 C54.1 L16.1 R215.2(N2) R232.2(N2) R244.1
UNNAMED_5_CAP_I47_N1: C49.1 C53.1 L15.1 R214.2(N2) R235.2(N2) R236.1
UNNAMED_5_CAP_I52_N1: C52.1 C56.1 L18.1 R231.2(N2) R234.2(N2) R246.1
UNNAMED_5_CAP_I71_N1: C51.1 C55.1 L17.1 R216.2(N2) R233.2(N2) R245.1
UNNAMED_5_CAP_I81_N2: C41.2(N2) R6.1
UNNAMED_5_CAP_I86_N2: C42.2(N2) R7.1
UNNAMED_5_CAP_I89_N2: C57.2(N2) R14.1
UNNAMED_5_CAP_I91_N2: C58.2(N2) R15.1
UNNAMED_5_CAP_I94_N2: C59.2(N2) R20.1
UNNAMED_5_CAP_I96_N2: C60.2(N2) R21.1
UNNAMED_5_CAP_I100_N2: C43.2(N2) R12.1
UNNAMED_5_CAP_I102_N2: C44.2(N2) R13.1
UNNAMED_5_CAP_I109_N1: C62.1 L37.2(N2) P2.3
UNNAMED_5_CAP_I110_N1: C61.1 L40.2(N2) P2.4
UNNAMED_5_CAP_I111_N1: C64.1 L39.2(N2) P2.1
UNNAMED_5_CAP_I112_N1: C63.1 L38.2(N2) P2.2
UNNAMED_5_CAP_I113_N1: C45.1 L30.2(N2) P1.2
UNNAMED_5_CAP_I114_N1: C46.1 L34.2(N2) P1.1
UNNAMED_5_CAP_I115_N1: C47.1 L35.2(N2) P1.4
UNNAMED_5_CAP_I116_N1: C48.1 L36.2(N2) P1.3
UNNAMED_5_CHOKE2P_I17_N1: L4.2(N2) L8.1 R11.1 R213.2(N2)
UNNAMED_5_CHOKE2P_I17_N2: L8.2(N2) L14.1 R11.2(N2)
UNNAMED_5_CHOKE2P_I22_N1: L3.2(N2) L7.1 R10.1 R212.2(N2)
UNNAMED_5_CHOKE2P_I22_N2: L7.2(N2) L13.1 R10.2(N2)
UNNAMED_5_CHOKE2P_I26_N1: L2.2(N2) L6.1 R9.1 R210.2(N2)
UNNAMED_5_CHOKE2P_I26_N2: L6.2(N2) L12.1 R9.2(N2)
UNNAMED_5_CHOKE2P_I37_N1: L1.2(N2) L5.1 R8.1 R209.2(N2)
UNNAMED_5_CHOKE2P_I37_N2: L5.2(N2) L9.1 R8.2(N2)
UNNAMED_5_CHOKE2P_I61_N1: L15.2(N2) L19.1 R16.1 R236.2(N2)
UNNAMED_5_CHOKE2P_I61_N2: L19.2(N2) L23.1 R16.2(N2)
UNNAMED_5_CHOKE2P_I65_N1: L18.2(N2) L22.1 R19.1 R246.2(N2)
UNNAMED_5_CHOKE2P_I65_N2: L22.2(N2) L26.1 R19.2(N2)
UNNAMED_5_CHOKE2P_I76_N1: L17.2(N2) L21.1 R18.1 R245.2(N2)
UNNAMED_5_CHOKE2P_I76_N2: L21.2(N2) L25.1 R18.2(N2)
UNNAMED_5_CHOKE2P_I80_N1: L16.2(N2) L20.1 R17.1 R244.2(N2)
UNNAMED_5_CHOKE2P_I80_N2: L20.2(N2) L24.1 R17.2(N2)
UNNAMED_5_IND_I125_N1: L9.2(N2) L30.1
UNNAMED_5_IND_I126_N1: L12.2(N2) L34.1
UNNAMED_5_IND_I127_N1: L13.2(N2) L35.1
UNNAMED_5_IND_I128_N1: L14.2(N2) L36.1
UNNAMED_5_IND_I129_N1: L25.2(N2) L38.1
UNNAMED_5_IND_I130_N1: L26.2(N2) L39.1
UNNAMED_5_IND_I131_N1: L23.2(N2) L40.1
UNNAMED_5_IND_I132_N1: L24.2(N2) L37.1
UNNAMED_6_CN240PABCD_I1_N1: P3.A1 R247.1
UNNAMED_6_CN240PABCD_I2_N36: P3.B36 R160.2(N2)
UNNAMED_6_CN240PABCD_I2_N37: P3.B37 R159.2(N2)
UNNAMED_6_CN240PABCD_I3_N34: P3.C34 R162.2(N2)
UNNAMED_6_CN240PABCD_I3_N35: P3.C35 R161.2(N2)
UNNAMED_6_CN240PABCD_I3_N36: P3.C36 R163.2(N2)
UNNAMED_6_CN240PABCD_I4_N34: P3.D34 R164.2(N2)
UNNAMED_8_CAP_I21_N1: C253.1 R135.1 U22.B3
UNNAMED_8_CN5P3SHLD_I32_N6: P10.SH1 P10.SH2 P10.SH3(N8) R180.1
UNNAMED_8_ICFT230XQ_I40_RESET: R181.2(N2) R182.1 U23.9
UNNAMED_9_741G126_I105_A: R27.2(N2) R29.2(N2) R185.2(N2) U14.2
UNNAMED_9_741G126_I105_Y: R37.1 U14.4(Y)
UNNAMED_9_AD9545_I1_CSB: R35.2(N2) R36.2(N2) U3.5
UNNAMED_9_AD9545_I1_LDO0: C96.1 C100.1 U3.7
UNNAMED_9_AD9545_I1_LDO1: C113.2(N2) C116.1 U3.30
UNNAMED_9_AD9545_I1_LF0: C100.2(N2) U3.8
UNNAMED_9_AD9545_I1_LF1: C113.1 U3.29
UNNAMED_9_AD9545_I1_M0: R43.2(N2) R44.1 U3.32
UNNAMED_9_AD9545_I1_M3: R40.2(N2) R204.1 U3.36
UNNAMED_9_AD9545_I1_M4: R38.2(N2) R39.1 U3.37
UNNAMED_9_AD9545_I1_REFA: R188.2(N2) R190.1 U3.47
UNNAMED_9_AD9545_I1_SCLK: R33.2(N2) U3.2
UNNAMED_9_AD9545_I1_SDIO: R34.2(N2) U3.4
UNNAMED_9_AD9545_I1_SDO: R32.2(N2) U3.1
UNNAMED_9_AD9545_I1_XOA: C108.2(N2) U3.42 Y3.3(N2)
UNNAMED_9_AD9545_I1_XOB: C107.1 U3.43(XOB) Y3.1
UNNAMED_9_ADM7154_I145_BYP: C225.1 U17.3
UNNAMED_9_ADM7154_I145_REF: C233.1 C234.1 R105.2(N2) U17.6
UNNAMED_9_ADM7154_I145_REFSENSE: R105.1 R227.1 U17.5
UNNAMED_9_ADM7154_I145_VOUT: C109.1 E2.1 U17.2
UNNAMED_9_ADM7154_I145_VREG: C118.1 U17.1(VREG)
UNNAMED_9_CNBNC5P_I111_CNTR: J1.1 R27.1
UNNAMED_9_CNBNC5P_I136_CNTR: J2.1 R28.1
UNNAMED_9_IC24XX16_I42_SCL: R54.1 U15.6
UNNAMED_9_IC24XX16_I42_SDA: R58.1 U15.5
UNNAMED_9_IC24XX16_I42_WP: R48.2(N2) R49.1 U15.7(WP)
UNNAMED_9_RES_I92_N2: R44.2(N2) Y4.3
UNNAMED_9_RES_I132_N1: R28.2(N2) R30.1 R31.1
UNNAMED_10_CAP_I6_N2: C120.2(N2) R46.2(N2) R47.1 R55.1
UNNAMED_10_CAP_I19_N2: C122.2(N2) R52.2(N2) R53.1 R57.1
UNNAMED_10_CAP_I32_N2: C267.2(N2) C268.2(N2) R89.1 R207.1 R208.1
UNNAMED_10_CAP_I47_N2: C148.2(N2) R86.2(N2) R87.1 R88.1
UNNAMED_10_CAP_I52_N2: C150.2(N2) J4.1
UNNAMED_10_CAP_I59_N2: C151.2(N2) R92.2(N2) R128.1 R139.1
UNNAMED_10_CNBNC5P_I40_CNTR: C149.2(N2) J3.1
UNNAMED_11_CAP_I29_N2: C126.2(N2) P4.12
UNNAMED_11_CAP_I30_N2: C121.2(N2) P4.13
UNNAMED_11_CAP_I31_N2: C142.2(N2) P4.18
UNNAMED_11_CAP_I32_N2: C125.2(N2) P4.19
UNNAMED_12_CN14P_I13_N2: D3.C P7.2
UNNAMED_12_DIOLED_I20_N: DS8.C R200.1
UNNAMED_12_DIOLED_I21_N: DS9.C R202.1
UNNAMED_12_DIOLED_I29_N: DS10.C R205.1
UNNAMED_12_DIOLED_I33_N: DS11.C R206.1
UNNAMED_12_DIOLED_I67_N: DS6.C R153.1
UNNAMED_12_RES_I17_N2: Q6.3 R200.2(N2)
UNNAMED_12_RES_I25_N2: Q12.3 R202.2(N2)
UNNAMED_12_RES_I28_N2: Q13.3 R205.2(N2)
UNNAMED_12_RES_I40_N1: R63.1 S1.3 S1.4(N4)
UNNAMED_12_RES_I42_N1: R64.1 S2.4B
UNNAMED_12_RES_I44_N1: R65.1 S2.3B
UNNAMED_12_RES_I46_N1: R66.1 S2.2B
UNNAMED_12_RES_I49_N1: R67.1 S6.3 S6.4(N4)
UNNAMED_12_RES_I51_N1: R68.1 S2.1B
UNNAMED_12_RES_I63_N1: R219.1 S3.3 S3.4(N4)
UNNAMED_12_RES_I68_N2: Q3.3 R153.2(N2)
UNNAMED_13_ADLTC330X_I1_AVIN: R73.2(N2) U6.12
UNNAMED_13_ADLTC330X_I1_FB: C135.2(N2) R78.2(N2) R79.1 U6.10
UNNAMED_13_ADLTC330X_I1_SW1: L29.1 U6.4 U6.5
UNNAMED_13_ADLTC330X_I31_AVIN: R72.2(N2) U5.12
UNNAMED_13_ADLTC330X_I31_FB: C145.2(N2) R76.2(N2) R77.1 U5.10
UNNAMED_13_ADLTC330X_I31_SW1: L28.1 U5.4 U5.5
UNNAMED_13_ADLTC330X_I33_AVIN: R71.2(N2) U4.12
UNNAMED_13_ADLTC330X_I33_FB: C147.2(N2) R74.2(N2) R75.1 U4.10
UNNAMED_13_ADLTC330X_I33_SW1: L27.1 U4.4 U4.5
UNNAMED_13_ADLTC330X_I92_AVIN: R228.2(N2) U18.12
UNNAMED_13_ADLTC330X_I92_FB: C146.2(N2) R229.2(N2) R230.1 U18.10
UNNAMED_13_ADLTC330X_I92_SW1: L32.1 U18.4 U18.5
UNNAMED_14_ADMAX3182X_I77_RSEL: R84.1 U7.B3
UNNAMED_14_ADMAX3182X_I78_RSEL: R85.1 U8.B3
UNNAMED_14_CN4P_I63_N3: P6.3 R101.2(N2) R103.1
UNNAMED_14_CN4P_I63_N4: D1.A(P) P6.4(N4) Q1.2 Q1.4
UNNAMED_14_RES_I58_N2: Q1.1 R98.2(N2)
UNNAMED_15_CN2P_I75_N2: F1.1 P8.2(N2)
UNNAMED_15_CN8PODDEVEN_I74_N3: P13.3 RT17.2(N2)
UNNAMED_15_CN8PODDEVEN_I74_N5: P13.5 RT18.2(N2)
UNNAMED_15_CN8PODDEVEN_I74_N7: P13.7 RT19.2(N2)
UNNAMED_15_CN16PODDEVEN_I72_N1: P12.2 RT9.1
UNNAMED_15_CN16PODDEVEN_I72_N2: P12.4 RT10.1
UNNAMED_15_CN16PODDEVEN_I72_N3: P12.6 RT11.1
UNNAMED_15_CN16PODDEVEN_I72_N4: P12.8 RT12.1
UNNAMED_15_CN16PODDEVEN_I72_N5: P12.10 RT13.1
UNNAMED_15_CN16PODDEVEN_I72_N6: P12.12 RT14.1
UNNAMED_15_CN16PODDEVEN_I72_N7: P12.14 RT15.1
UNNAMED_15_CN16PODDEVEN_I72_N8: P12.16(N8) RT16.1
UNNAMED_15_CN16PODDEVEN_I73_N1: P12.1 RT1.1
UNNAMED_15_CN16PODDEVEN_I73_N2: P12.3 RT2.1
UNNAMED_15_CN16PODDEVEN_I73_N3: P12.5 RT3.1
UNNAMED_15_CN16PODDEVEN_I73_N4: P12.7 RT4.1
UNNAMED_15_CN16PODDEVEN_I73_N5: P12.9 RT5.1
UNNAMED_15_CN16PODDEVEN_I73_N6: P12.11 RT6.1
UNNAMED_15_CN16PODDEVEN_I73_N7: P12.13 RT7.1
UNNAMED_15_CN16PODDEVEN_I73_N8: P12.15 RT8.1
UNNAMED_17_ADLTC4355_I29_GATE1: Q4.4 U27.2
UNNAMED_17_ADLTC4355_I29_GATE2: Q8.4 U27.4
UNNAMED_17_ADLTC4355_I29_IN2: FL1.2 Q8.1 Q8.2 Q8.3(S3) R221.1 U27.5
UNNAMED_17_ADLTC4355_I29_MON1: R221.2(N2) R222.1 U27.14
UNNAMED_17_ADLTC4355_I29_MON2: R223.2(N2) R224.1 U27.9
UNNAMED_17_ADLTC4355_I29_SET: R225.1 U27.8
UNNAMED_17_ADLTC4355_I29_VDSFLTN: R226.1 U27.6(VDSFLT_N)
UNNAMED_17_ADMAX2520X_I70_BST: C229.1 U10.18
UNNAMED_17_ADMAX2520X_I70_COMP: R102.1 U10.6
UNNAMED_17_ADMAX2520X_I70_CS: C230.1 R108.2(N2) U10.10
UNNAMED_17_ADMAX2520X_I70_DH: R106.1 U10.17
UNNAMED_17_ADMAX2520X_I70_DL: R107.1 U10.15
UNNAMED_17_ADMAX2520X_I70_FB: R110.1 R112.2(N2) R237.1 U10.8
UNNAMED_17_ADMAX2520X_I70_FOSC: R99.1 U10.4
UNNAMED_17_ADMAX2520X_I70_FSYNC: R93.2(N2) R94.1 R95.1 U10.3
UNNAMED_17_ADMAX2520X_I70_LX: C229.2(N2) L31.1 Q5.5 Q7.1 Q7.2 Q7.3(S3) U10.16
UNNAMED_17_ADMAX2520X_I70_OUT: C230.2(N2) R111.2(N2) U10.9
UNNAMED_17_ADMAX2520X_I70_PGOOD: R249.2(N2) U10.5
UNNAMED_17_ADMAX2520X_I70_SPS: R96.2(N2) R97.1 U10.1
UNNAMED_17_ADMAX17573_I106_BST: C247.2(N2) U21.22
UNNAMED_17_ADMAX17573_I106_MODE: R239.1 R240.1 R241.1 U21.15
UNNAMED_17_ADMAX17573_I106_RESETN: R250.2(N2) U21.14
UNNAMED_17_ADMAX17573_I106_RT: R238.1 U21.19
UNNAMED_17_ADMAX17573_I106_SS: C248.1 U21.16
UNNAMED_17_CAP_I8_N1: C240.1 FL1.1 P11.1 P11.4
UNNAMED_17_CAP_I8_N2: C240.2(N2) FL1.3(PSG) P11.3 P11.6(N6)
UNNAMED_17_CAP_I66_N1: C227.1 R102.2(N2)
UNNAMED_17_IND_I90_N2: L31.2(N2) R108.1 R109.1
UNNAMED_17_RES_I48_N2: R141.2(N2) S12.2
UNNAMED_17_RES_I79_N2: Q7.4 R106.2(N2)
UNNAMED_17_RES_I83_N2: Q5.4 R107.2(N2)
USB_DEBUG_N: D4.C P10.2 U23.7
USB_DEBUG_P: D5.C P10.3 U23.6
VCAM_9V0: C26.1 C87.1 C251.1 C252.1 L33.2(N2) R195.1 R196.1 R197.1 R198.1 R232.1 R233.1 R234.1 R235.1 R242.1 U12.2 U12.3 U12.4 U13.2 U13.3 U13.4

Pads without a net: P3 A9 A10 A12 A13 A31 A32 A34 A35 A36 A38 A39 A40 A42 A43 A44 A47 A48 A51 A52 A55 A56 B2 B8 B20 B21 B22 B28 B32 B34 B38 B40 B41 B42 B44 B45 B46 B49 B50 B53 B54 B57 B58 C3 C4 C6 C7 C9 C10 C24 C26 C27 C28 C30 C31 C32 C38 C39 C40 C42 C43 C44 C45 C47 C48 C51 C52 C55 C56 D4 D5 D7 D8 D10 D11 D13 D14 D22 D24 D25 D26 D28 D29 D30 D32 D36 D37 D38 D40 D41 D42 D44 D45 D46 D49 D50 D53 D54 D57 D58; P5 A3 A4 A7 A8 A29 A30 A32 A33 A35 A36 A38 A39 A41 A42 A55 A56 A58 A59 A60 B9 B10 B27 B28 B30 B31 B33 B34 B36 B37 B39 B40 B54 B56 B57 B58 C7 C8 C26 C27 C29 C30 C32 C33 C35 C36 C38 C39 C41 C42 C54 C55 C56 C58 C59 C60 D1 D2 D5 D6 D9 D10 D18 D19 D27 D28 D30 D31 D33 D34 D36 D37 D39 D40 D52 D53 D54 D56 D57 D58; P7 12 14; P10 4; P11 2 5; S12 1; U1 33 34 51 52; U2 33 34 51 52; U3 16 21 44 46; U7 A1; U8 A1; U10 11; U12 8 17 18; U13 8 17 18; U15 1 2 3; U19 16 17; U21 4 8 13 17; U22 E2; U23 4 5 11 12 14 16; Y4 1

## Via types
v1: diameter 0.508, hole 0.254, TOP to BOTTOM, 1423 vias
v2: diameter 0.406, hole 0.203, TOP to BOTTOM, 493 vias
v3: diameter 0.406, hole 0.203, TOP to L2_GND, 90 vias
v4: diameter 0.406, hole 0.203, L2_GND to L3_SIG, 38 vias
v5: diameter 0.305, hole 0.152, TOP to BOTTOM, 5 vias
v6: diameter 0.406, hole 0.203, L8_SIG to L9_GND, 32 vias
v7: diameter 0.406, hole 0.203, L9_GND to BOTTOM, 46 vias

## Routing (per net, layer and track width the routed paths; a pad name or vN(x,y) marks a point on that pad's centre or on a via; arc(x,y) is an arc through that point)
1V2: length 22.6
  TOP w0.305: v1(21.26,40.67) 23.31,38.62 v1(27.63,38.62)
  TOP w0.356: P5.A44 v4(95.37,25.45) ; P5.C44 95.37,27.97 v4(95.38,27.97) ; P5.B42 v4(94.1,27.36) ; P5.D42 94.1,29.92 v4(94.11,29.92)
  TOP w0.508: v1(28.39,37.86) v1(27.63,37.86) v1(27.63,38.62) ; v1(28.39,37.86) v1(27.63,38.62) ; v1(28.39,37.86) v1(28.39,38.62) v1(27.63,38.62)
  L5_PWR w0.508: TP6.1 120.29,61.3 ; TP6.1 120.29,58.64 ; TP6.1 121.63,59.97 ; TP6.1 118.96,59.97
  BOTTOM w0.305: U2.55 109.19,42.98 109.19,43.3 ; U1.55 109.37,86.94 109.37,87.37 ; C135.1 22.07,42.21 R78.1 v1(21.26,40.67)
  vias: v1(94.55,24.59) v1(94.55,23.87) v1(94.77,22.11) v1(94.77,21.35) v1(106.25,47.35) v1(106.78,47.83) v1(106.96,90.47) v1(107.44,89.94) v1(109,26.96) v1(109.38,71.21) v1(109.54,27.5) v1(109.92,71.75)
1V8: length 85.7
  TOP w0.305: U25.1 C123.1 v1(120.41,24.54) ; R191.1 v1(89.74,100.97) ; R36.1 95.33,100 v2(96.24,100.91) ; U3.3 v2(95.11,101.83) ; v1(39.04,40.72) 41.14,38.62 v1(45.41,38.62) ; v1(118.03,68.34) 118.04,68.33 C114.1 U20.1 ; 132.97,60.12 U19.21 ; U24.10 C263.1 87.38,16.33 v1(87.63,16.59)
  TOP w0.356: v1(106.66,28.44) 109.38,31.17 R177.1 ; P3.D2 P3.D1
  TOP w0.483: R117.1 R120.1 R119.1 v1(128.98,62.46) ; R121.1 R142.1 ; 133.94,65.45 R113.1 ; R41.1 v1(114.71,68.15) 114.71,68.47 R166.1 ; v1(120.41,24.54) 120.41,24.55 R175.1 ; v1(118.03,68.34) R167.1 ; v1(132.21,59.56) C235.1 132.97,60.12 ; R137.1 R138.1 R129.1 R134.1 141.91,57.61 140.69,56.39 v1(139.88,56.39) ; v1(117.41,24.38) R158.1
  TOP w0.508: 118.2,47.73 R70.1 ; 118.2,47.73 118.2,49.78 117.72,50.27 R115.1 ; 118.2,47.73 v1(119.04,46.89) ; v1(46.17,37.86) v1(45.41,37.86) v1(45.41,38.62) ; v1(46.17,37.86) v1(46.17,38.62) v1(45.41,38.62) ; v1(46.17,37.86) v1(45.41,38.62) ; P3.D1 v1(67.55,96.56) v1(66.92,96.56) ; R218.1 135.05,11.76 132.84,11.76 131.98,12.62 v1(131.98,13.26) ; P5.D59 P5.D60 105.67,29.43 v1(106.66,28.44) v1(106.66,27.73) 105.82,26.89 P5.B60 P5.B59 ; R142.1 130.48,57.11 v1(130.48,57.11) ; R168.1 115.89,89.43 R172.1 ; 133.94,65.45 134.77,66.27 v1(137.91,66.27)
  TOP w0.61: R4.2 v1(119.04,73.65) v1(120.01,73.65) 120.02,73.65 R170.1 ; R25.2 119.69,29.43 v1(118.96,29.43) v1(118.25,29.43) ; 119.87,46.89 119.25,46.28 R22.1 v1(119.04,46.89) 119.87,46.89 ; 119.87,46.89 v1(119.87,46.89) ; R172.1 118.06,90.58 v1(118.31,90.83) v1(119.04,90.83) R1.1
  BOTTOM w0.203: U22.A2 72.55,18.28 v1(72.16,18.67)
  BOTTOM w0.305: C145.1 39.85,42.21 R76.1 v1(39.04,40.72)
  BOTTOM w0.406: R131.1 R130.1 72.69,21.47 74.45,21.47 74.66,21.26 R333.1 v1(74.66,20.19) ; v1(76.68,18.1) R132.1 R332.1 ; v2(95.11,101.83) C110.1
  BOTTOM w0.508: C255.1 v1(72.16,18.67) ; R136.1 v1(55.73,7.2)
  vias: v1(48.34,96.32) v1(48.34,95.55) v1(116.79,94.17) v1(116.79,93.41) v1(117.55,94.17) v1(117.55,93.41)
